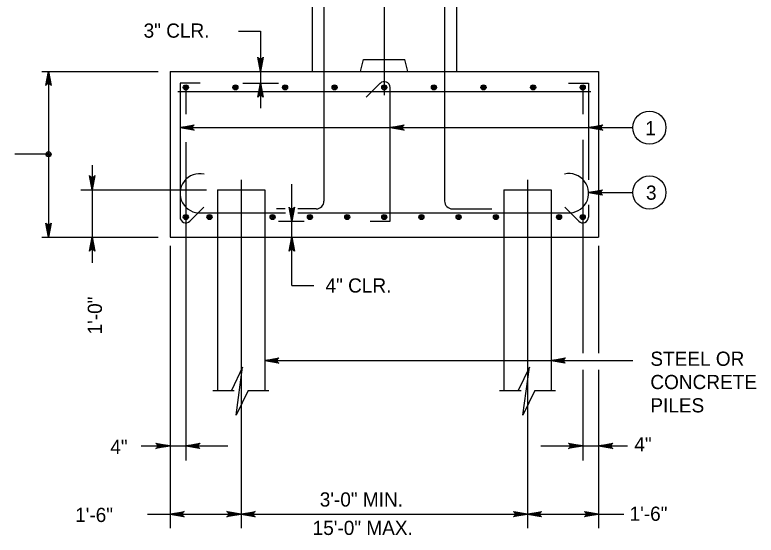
# Model space of a CAD drawing. Extents: x 646165 to 651486, y 296916 to 299292.
# Drawn here: x 650911.5 to 651068, y 299114.9 to 299224.8 of the extents above; entities that cross this region are included whole.
import ezdxf

# ---------------------------------------------------------------- set-up
doc = ezdxf.new("R2010")
doc.units = 0
for name, color, linetype in [('50', 7, 'Continuous'), ('51', 7, 'Continuous'), ('52', 7, 'Continuous'), ('53', 7, 'Continuous'), ('54', 7, 'Continuous'), ('61', 7, 'Continuous')]:
    doc.layers.add(name, color=color, linetype=linetype)

msp = doc.modelspace()

# ---------------------------------------------------------------- linework, layer by layer
at = {"layer": '50'}
for p, q in [((650989.51, 299253.96), (650989.51, 299207.88)), ((650947.61, 299197.9), (650947.61, 299130.73)), ((651031.41, 299198.39), (651031.41, 299153.4)), ((650959.28, 299190.01), (650959.28, 299116.44)), ((651019.74, 299190.01), (651019.74, 299116.44)), ((651031.41, 299149.83), (651031.41, 299130.73))]:
    msp.add_line(p, q, dxfattribs=at)
at = {"layer": '51'}
for p, q in [((650974.28, 299257.98), (650974.28, 299212.88)), ((651004.74, 299257.98), (651004.74, 299212.88)), ((650984.51, 299212.88), (650985.15, 299215.38)), ((650985.15, 299215.38), (650993.87, 299215.38)), ((650994.51, 299212.88), (650993.87, 299215.38)), ((650944.28, 299212.88), (650944.28, 299177.88)), ((650944.28, 299212.88), (651034.74, 299212.88)), ((651034.74, 299212.88), (651034.74, 299177.88)), ((650944.28, 299177.88), (651034.74, 299177.88))]:
    msp.add_line(p, q, dxfattribs=at)
at = {"layer": '52'}
for p, q in [((650958.74, 299221.35), (650963.37, 299221.35)), ((650963.37, 299221.35), (650963.37, 299205.12)), ((650917.23, 299212.88), (650941.76, 299212.88)), ((650918.62, 299212.88), (650918.62, 299177.88)), ((650959.62, 299210.38), (650967.15, 299210.38)), ((650947.61, 299209.49), (650947.61, 299203.87)), ((651031.41, 299209.49), (651031.41, 299203.87)), ((650946.39, 299201), (651041.98, 299201)), ((650918.62, 299195.38), (650911.51, 299195.38)), ((650927.85, 299193.04), (650927.85, 299172.45)), ((650969.96, 299167.66), (650969.96, 299189.04)), ((650925.44, 299187.88), (650952.01, 299187.88)), ((651032.63, 299187.31), (651041.98, 299187.31)), ((650967.2, 299181.22), (650972.62, 299181.22)), ((650917.23, 299177.88), (650941.76, 299177.88)), ((650944.28, 299176.06), (650944.28, 299116.44)), ((651034.74, 299176.06), (651034.74, 299153.4)), ((650969.96, 299167.66), (650974.66, 299167.66)), ((650964.28, 299151.8), (651041.98, 299151.8)), ((651034.74, 299149.83), (651034.74, 299116.44)), ((650953.29, 299145.48), (650957.85, 299145.48)), ((650960.77, 299145.48), (650965.11, 299145.48)), ((651013.82, 299145.48), (651018.38, 299145.48)), ((651021.3, 299145.48), (651025.63, 299145.48)), ((650938.21, 299133.78), (650956.5, 299133.78)), ((651022.53, 299133.78), (651040.88, 299133.78)), ((650939.49, 299119.38), (650959.28, 299119.38)), ((650959.28, 299119.38), (651019.74, 299119.38)), ((651019.74, 299119.38), (651040.11, 299119.38))]:
    msp.add_line(p, q, dxfattribs=at)
for points in [[(650963.37, 299212.88), (650962.81, 299215.87), (650962.89, 299215.75), (650962.97, 299215.64), (650963.07, 299215.58), (650963.17, 299215.52), (650963.27, 299215.5), (650963.37, 299215.48), (650963.47, 299215.5), (650963.57, 299215.52), (650963.67, 299215.58), (650963.77, 299215.64), (650963.85, 299215.75), (650963.93, 299215.87), (650963.37, 299212.88), (650963.85, 299215.75), (650963.77, 299215.64), (650963.37, 299212.88), (650963.67, 299215.58), (650963.57, 299215.52), (650963.37, 299212.88), (650963.47, 299215.5), (650963.37, 299215.48), (650963.37, 299212.88), (650963.27, 299215.5), (650963.17, 299215.52), (650963.37, 299212.88), (650963.07, 299215.58), (650962.97, 299215.64), (650963.37, 299212.88), (650962.89, 299215.75)], [(650918.62, 299212.88), (650919.18, 299209.9), (650919.1, 299210.02), (650919.02, 299210.13), (650918.92, 299210.19), (650918.82, 299210.25), (650918.72, 299210.27), (650918.62, 299210.28), (650918.52, 299210.27), (650918.42, 299210.25), (650918.32, 299210.19), (650918.22, 299210.13), (650918.14, 299210.02), (650918.06, 299209.9), (650918.62, 299212.88), (650918.14, 299210.02), (650918.22, 299210.13), (650918.62, 299212.88), (650918.32, 299210.19), (650918.42, 299210.25), (650918.62, 299212.88), (650918.52, 299210.27), (650918.62, 299210.28), (650918.62, 299212.88), (650918.72, 299210.27), (650918.82, 299210.25), (650918.62, 299212.88), (650918.92, 299210.19), (650919.02, 299210.13), (650918.62, 299212.88), (650919.1, 299210.02)], [(650963.37, 299210.38), (650963.93, 299207.4), (650963.85, 299207.52), (650963.77, 299207.63), (650963.67, 299207.69), (650963.57, 299207.75), (650963.47, 299207.77), (650963.37, 299207.78), (650963.27, 299207.77), (650963.17, 299207.75), (650963.07, 299207.69), (650962.97, 299207.63), (650962.89, 299207.52), (650962.81, 299207.4), (650963.37, 299210.38), (650962.89, 299207.52), (650962.97, 299207.63), (650963.37, 299210.38), (650963.07, 299207.69), (650963.17, 299207.75), (650963.37, 299210.38), (650963.27, 299207.77), (650963.37, 299207.78), (650963.37, 299210.38), (650963.47, 299207.77), (650963.57, 299207.75), (650963.37, 299210.38), (650963.67, 299207.69), (650963.77, 299207.63), (650963.37, 299210.38), (650963.85, 299207.52)], [(650946.39, 299201), (650949.37, 299201.56), (650949.25, 299201.48), (650949.14, 299201.4), (650949.08, 299201.3), (650949.02, 299201.2), (650949, 299201.1), (650948.99, 299201), (650949, 299200.9), (650949.02, 299200.8), (650949.08, 299200.7), (650949.14, 299200.6), (650949.25, 299200.52), (650949.37, 299200.44), (650946.39, 299201), (650949.25, 299200.52), (650949.14, 299200.6), (650946.39, 299201), (650949.08, 299200.7), (650949.02, 299200.8), (650946.39, 299201), (650949, 299200.9), (650948.99, 299201), (650946.39, 299201), (650949, 299201.1), (650949.02, 299201.2), (650946.39, 299201), (650949.08, 299201.3), (650949.14, 299201.4), (650946.39, 299201), (650949.25, 299201.48)], [(650990.73, 299201), (650993.71, 299201.56), (650993.6, 299201.48), (650993.49, 299201.4), (650993.43, 299201.3), (650993.37, 299201.2), (650993.35, 299201.1), (650993.33, 299201), (650993.35, 299200.9), (650993.37, 299200.8), (650993.43, 299200.7), (650993.49, 299200.6), (650993.6, 299200.52), (650993.71, 299200.44), (650990.73, 299201), (650993.6, 299200.52), (650993.49, 299200.6), (650990.73, 299201), (650993.43, 299200.7), (650993.37, 299200.8), (650990.73, 299201), (650993.35, 299200.9), (650993.33, 299201), (650990.73, 299201), (650993.35, 299201.1), (650993.37, 299201.2), (650990.73, 299201), (650993.43, 299201.3), (650993.49, 299201.4), (650990.73, 299201), (650993.6, 299201.48)], [(651032.63, 299201), (651035.62, 299201.56), (651035.5, 299201.48), (651035.39, 299201.4), (651035.33, 299201.3), (651035.27, 299201.2), (651035.25, 299201.1), (651035.23, 299201), (651035.25, 299200.9), (651035.27, 299200.8), (651035.33, 299200.7), (651035.39, 299200.6), (651035.5, 299200.52), (651035.62, 299200.44), (651032.63, 299201), (651035.5, 299200.52), (651035.39, 299200.6), (651032.63, 299201), (651035.33, 299200.7), (651035.27, 299200.8), (651032.63, 299201), (651035.25, 299200.9), (651035.23, 299201), (651032.63, 299201), (651035.25, 299201.1), (651035.27, 299201.2), (651032.63, 299201), (651035.33, 299201.3), (651035.39, 299201.4), (651032.63, 299201), (651035.5, 299201.48)], [(650927.85, 299187.88), (650927.29, 299190.87), (650927.37, 299190.75), (650927.45, 299190.64), (650927.55, 299190.58), (650927.65, 299190.52), (650927.75, 299190.5), (650927.85, 299190.48), (650927.95, 299190.5), (650928.05, 299190.52), (650928.15, 299190.58), (650928.25, 299190.64), (650928.33, 299190.75), (650928.41, 299190.87), (650927.85, 299187.88), (650928.33, 299190.75), (650928.25, 299190.64), (650927.85, 299187.88), (650928.15, 299190.58), (650928.05, 299190.52), (650927.85, 299187.88), (650927.95, 299190.5), (650927.85, 299190.48), (650927.85, 299187.88), (650927.75, 299190.5), (650927.65, 299190.52), (650927.85, 299187.88), (650927.55, 299190.58), (650927.45, 299190.64), (650927.85, 299187.88), (650927.37, 299190.75)], [(651032.63, 299187.31), (651035.61, 299187.87), (651035.5, 299187.79), (651035.39, 299187.71), (651035.33, 299187.61), (651035.27, 299187.51), (651035.25, 299187.41), (651035.23, 299187.31), (651035.25, 299187.21), (651035.27, 299187.11), (651035.33, 299187.01), (651035.39, 299186.91), (651035.5, 299186.83), (651035.61, 299186.75), (651032.63, 299187.31), (651035.5, 299186.83), (651035.39, 299186.91), (651032.63, 299187.31), (651035.33, 299187.01), (651035.27, 299187.11), (651032.63, 299187.31), (651035.25, 299187.21), (651035.23, 299187.31), (651032.63, 299187.31), (651035.25, 299187.41), (651035.27, 299187.51), (651032.63, 299187.31), (651035.33, 299187.61), (651035.39, 299187.71), (651032.63, 299187.31), (651035.5, 299187.79)], [(650969.96, 299181.22), (650969.4, 299184.2), (650969.48, 299184.08), (650969.56, 299183.97), (650969.66, 299183.91), (650969.76, 299183.85), (650969.86, 299183.83), (650969.96, 299183.82), (650970.06, 299183.83), (650970.16, 299183.85), (650970.26, 299183.91), (650970.36, 299183.97), (650970.44, 299184.08), (650970.52, 299184.2), (650969.96, 299181.22), (650970.44, 299184.08), (650970.36, 299183.97), (650969.96, 299181.22), (650970.26, 299183.91), (650970.16, 299183.85), (650969.96, 299181.22), (650970.06, 299183.83), (650969.96, 299183.82), (650969.96, 299181.22), (650969.86, 299183.83), (650969.76, 299183.85), (650969.96, 299181.22), (650969.66, 299183.91), (650969.56, 299183.97), (650969.96, 299181.22), (650969.48, 299184.08)], [(650918.62, 299177.88), (650918.06, 299180.86), (650918.14, 299180.75), (650918.22, 299180.63), (650918.32, 299180.58), (650918.42, 299180.52), (650918.52, 299180.5), (650918.62, 299180.48), (650918.72, 299180.5), (650918.82, 299180.52), (650918.92, 299180.58), (650919.02, 299180.63), (650919.1, 299180.75), (650919.18, 299180.86), (650918.62, 299177.88), (650919.1, 299180.75), (650919.02, 299180.63), (650918.62, 299177.88), (650918.92, 299180.58), (650918.82, 299180.52), (650918.62, 299177.88), (650918.72, 299180.5), (650918.62, 299180.48), (650918.62, 299177.88), (650918.52, 299180.5), (650918.42, 299180.52), (650918.62, 299177.88), (650918.32, 299180.58), (650918.22, 299180.63), (650918.62, 299177.88), (650918.14, 299180.75)], [(650918.62, 299177.88), (650918.06, 299180.86), (650918.14, 299180.75), (650918.22, 299180.63), (650918.32, 299180.58), (650918.42, 299180.52), (650918.52, 299180.5), (650918.62, 299180.48), (650918.72, 299180.5), (650918.82, 299180.52), (650918.92, 299180.58), (650919.02, 299180.63), (650919.1, 299180.75), (650919.18, 299180.86), (650918.62, 299177.88), (650919.1, 299180.75), (650919.02, 299180.63), (650918.62, 299177.88), (650918.92, 299180.58), (650918.82, 299180.52), (650918.62, 299177.88), (650918.72, 299180.5), (650918.62, 299180.48), (650918.62, 299177.88), (650918.52, 299180.5), (650918.42, 299180.52), (650918.62, 299177.88), (650918.32, 299180.58), (650918.22, 299180.63), (650918.62, 299177.88), (650918.14, 299180.75)], [(650927.85, 299177.88), (650928.41, 299174.9), (650928.33, 299175.01), (650928.25, 299175.13), (650928.15, 299175.19), (650928.05, 299175.25), (650927.95, 299175.27), (650927.85, 299175.28), (650927.75, 299175.27), (650927.65, 299175.25), (650927.55, 299175.19), (650927.45, 299175.13), (650927.37, 299175.01), (650927.29, 299174.9), (650927.85, 299177.88), (650927.37, 299175.01), (650927.45, 299175.13), (650927.85, 299177.88), (650927.55, 299175.19), (650927.65, 299175.25), (650927.85, 299177.88), (650927.75, 299175.27), (650927.85, 299175.28), (650927.85, 299177.88), (650927.95, 299175.27), (650928.05, 299175.25), (650927.85, 299177.88), (650928.15, 299175.19), (650928.25, 299175.13), (650927.85, 299177.88), (650928.33, 299175.01)], [(650969.96, 299177.88), (650970.52, 299174.9), (650970.44, 299175.01), (650970.36, 299175.13), (650970.26, 299175.19), (650970.16, 299175.25), (650970.06, 299175.27), (650969.96, 299175.28), (650969.86, 299175.27), (650969.76, 299175.25), (650969.66, 299175.19), (650969.56, 299175.13), (650969.48, 299175.01), (650969.4, 299174.9), (650969.96, 299177.88), (650969.48, 299175.01), (650969.56, 299175.13), (650969.96, 299177.88), (650969.66, 299175.19), (650969.76, 299175.25), (650969.96, 299177.88), (650969.86, 299175.27), (650969.96, 299175.28), (650969.96, 299177.88), (650970.06, 299175.27), (650970.16, 299175.25), (650969.96, 299177.88), (650970.26, 299175.19), (650970.36, 299175.13), (650969.96, 299177.88), (650970.44, 299175.01)], [(650964.28, 299151.8), (650967.26, 299152.36), (650967.14, 299152.28), (650967.03, 299152.2), (650966.97, 299152.1), (650966.91, 299152), (650966.89, 299151.9), (650966.88, 299151.8), (650966.89, 299151.7), (650966.91, 299151.6), (650966.97, 299151.5), (650967.03, 299151.4), (650967.14, 299151.32), (650967.26, 299151.24), (650964.28, 299151.8), (650967.14, 299151.32), (650967.03, 299151.4), (650964.28, 299151.8), (650966.97, 299151.5), (650966.91, 299151.6), (650964.28, 299151.8), (650966.89, 299151.7), (650966.88, 299151.8), (650964.28, 299151.8), (650966.89, 299151.9), (650966.91, 299152), (650964.28, 299151.8), (650966.97, 299152.1), (650967.03, 299152.2), (650964.28, 299151.8), (650967.14, 299152.28)], [(651024.74, 299151.8), (651027.73, 299152.36), (651027.61, 299152.28), (651027.5, 299152.2), (651027.44, 299152.1), (651027.38, 299152), (651027.36, 299151.9), (651027.34, 299151.8), (651027.36, 299151.7), (651027.38, 299151.6), (651027.44, 299151.5), (651027.5, 299151.4), (651027.61, 299151.32), (651027.73, 299151.24), (651024.74, 299151.8), (651027.61, 299151.32), (651027.5, 299151.4), (651024.74, 299151.8), (651027.44, 299151.5), (651027.38, 299151.6), (651024.74, 299151.8), (651027.36, 299151.7), (651027.34, 299151.8), (651024.74, 299151.8), (651027.36, 299151.9), (651027.38, 299152), (651024.74, 299151.8), (651027.44, 299152.1), (651027.5, 299152.2), (651024.74, 299151.8), (651027.61, 299152.28)], [(650960.77, 299145.48), (650958.23, 299140.29), (650959.61, 299150.44), (650957.25, 299145.48)], [(651021.3, 299145.48), (651018.76, 299140.29), (651020.14, 299150.44), (651017.78, 299145.48)], [(650944.28, 299133.78), (650941.29, 299133.22), (650941.41, 299133.3), (650941.52, 299133.38), (650941.58, 299133.48), (650941.64, 299133.58), (650941.66, 299133.68), (650941.68, 299133.78), (650941.66, 299133.88), (650941.64, 299133.98), (650941.58, 299134.08), (650941.52, 299134.18), (650941.41, 299134.26), (650941.29, 299134.34), (650944.28, 299133.78), (650941.41, 299134.26), (650941.52, 299134.18), (650944.28, 299133.78), (650941.58, 299134.08), (650941.64, 299133.98), (650944.28, 299133.78), (650941.66, 299133.88), (650941.68, 299133.78), (650944.28, 299133.78), (650941.66, 299133.68), (650941.64, 299133.58), (650944.28, 299133.78), (650941.58, 299133.48), (650941.52, 299133.38), (650944.28, 299133.78), (650941.41, 299133.3)], [(650947.61, 299133.78), (650950.59, 299134.34), (650950.48, 299134.26), (650950.36, 299134.18), (650950.3, 299134.08), (650950.24, 299133.98), (650950.23, 299133.88), (650950.21, 299133.78), (650950.23, 299133.68), (650950.24, 299133.58), (650950.3, 299133.48), (650950.36, 299133.38), (650950.48, 299133.3), (650950.59, 299133.22), (650947.61, 299133.78), (650950.48, 299133.3), (650950.36, 299133.38), (650947.61, 299133.78), (650950.3, 299133.48), (650950.24, 299133.58), (650947.61, 299133.78), (650950.23, 299133.68), (650950.21, 299133.78), (650947.61, 299133.78), (650950.23, 299133.88), (650950.24, 299133.98), (650947.61, 299133.78), (650950.3, 299134.08), (650950.36, 299134.18), (650947.61, 299133.78), (650950.48, 299134.26)], [(651031.41, 299133.78), (651028.43, 299133.22), (651028.54, 299133.3), (651028.66, 299133.38), (651028.72, 299133.48), (651028.78, 299133.58), (651028.79, 299133.68), (651028.81, 299133.78), (651028.79, 299133.88), (651028.78, 299133.98), (651028.72, 299134.08), (651028.66, 299134.18), (651028.54, 299134.26), (651028.43, 299134.34), (651031.41, 299133.78), (651028.54, 299134.26), (651028.66, 299134.18), (651031.41, 299133.78), (651028.72, 299134.08), (651028.78, 299133.98), (651031.41, 299133.78), (651028.79, 299133.88), (651028.81, 299133.78), (651031.41, 299133.78), (651028.79, 299133.68), (651028.78, 299133.58), (651031.41, 299133.78), (651028.72, 299133.48), (651028.66, 299133.38), (651031.41, 299133.78), (651028.54, 299133.3)], [(651034.74, 299133.78), (651037.73, 299134.34), (651037.61, 299134.26), (651037.5, 299134.18), (651037.44, 299134.08), (651037.38, 299133.98), (651037.36, 299133.88), (651037.34, 299133.78), (651037.36, 299133.68), (651037.38, 299133.58), (651037.44, 299133.48), (651037.5, 299133.38), (651037.61, 299133.3), (651037.73, 299133.22), (651034.74, 299133.78), (651037.61, 299133.3), (651037.5, 299133.38), (651034.74, 299133.78), (651037.44, 299133.48), (651037.38, 299133.58), (651034.74, 299133.78), (651037.36, 299133.68), (651037.34, 299133.78), (651034.74, 299133.78), (651037.36, 299133.88), (651037.38, 299133.98), (651034.74, 299133.78), (651037.44, 299134.08), (651037.5, 299134.18), (651034.74, 299133.78), (651037.61, 299134.26)], [(650944.28, 299119.38), (650947.26, 299119.94), (650947.14, 299119.86), (650947.03, 299119.78), (650946.97, 299119.68), (650946.91, 299119.58), (650946.89, 299119.48), (650946.88, 299119.38), (650946.89, 299119.28), (650946.91, 299119.18), (650946.97, 299119.08), (650947.03, 299118.98), (650947.14, 299118.9), (650947.26, 299118.82), (650944.28, 299119.38), (650947.14, 299118.9), (650947.03, 299118.98), (650944.28, 299119.38), (650946.97, 299119.08), (650946.91, 299119.18), (650944.28, 299119.38), (650946.89, 299119.28), (650946.88, 299119.38), (650944.28, 299119.38), (650946.89, 299119.48), (650946.91, 299119.58), (650944.28, 299119.38), (650946.97, 299119.68), (650947.03, 299119.78), (650944.28, 299119.38), (650947.14, 299119.86)], [(650959.28, 299119.38), (650956.29, 299118.82), (650956.41, 299118.9), (650956.52, 299118.98), (650956.58, 299119.08), (650956.64, 299119.18), (650956.66, 299119.28), (650956.68, 299119.38), (650956.66, 299119.48), (650956.64, 299119.58), (650956.58, 299119.68), (650956.52, 299119.78), (650956.41, 299119.86), (650956.29, 299119.94), (650959.28, 299119.38), (650956.41, 299119.86), (650956.52, 299119.78), (650959.28, 299119.38), (650956.58, 299119.68), (650956.64, 299119.58), (650959.28, 299119.38), (650956.66, 299119.48), (650956.68, 299119.38), (650959.28, 299119.38), (650956.66, 299119.28), (650956.64, 299119.18), (650959.28, 299119.38), (650956.58, 299119.08), (650956.52, 299118.98), (650959.28, 299119.38), (650956.41, 299118.9)], [(650959.28, 299119.38), (650962.26, 299119.94), (650962.14, 299119.86), (650962.03, 299119.78), (650961.97, 299119.68), (650961.91, 299119.58), (650961.89, 299119.48), (650961.88, 299119.38), (650961.89, 299119.28), (650961.91, 299119.18), (650961.97, 299119.08), (650962.03, 299118.98), (650962.14, 299118.9), (650962.26, 299118.82), (650959.28, 299119.38), (650962.14, 299118.9), (650962.03, 299118.98), (650959.28, 299119.38), (650961.97, 299119.08), (650961.91, 299119.18), (650959.28, 299119.38), (650961.89, 299119.28), (650961.88, 299119.38), (650959.28, 299119.38), (650961.89, 299119.48), (650961.91, 299119.58), (650959.28, 299119.38), (650961.97, 299119.68), (650962.03, 299119.78), (650959.28, 299119.38), (650962.14, 299119.86)], [(651019.74, 299119.38), (651016.76, 299118.82), (651016.88, 299118.9), (651016.99, 299118.98), (651017.05, 299119.08), (651017.11, 299119.18), (651017.13, 299119.28), (651017.14, 299119.38), (651017.13, 299119.48), (651017.11, 299119.58), (651017.05, 299119.68), (651016.99, 299119.78), (651016.88, 299119.86), (651016.76, 299119.94), (651019.74, 299119.38), (651016.88, 299119.86), (651016.99, 299119.78), (651019.74, 299119.38), (651017.05, 299119.68), (651017.11, 299119.58), (651019.74, 299119.38), (651017.13, 299119.48), (651017.14, 299119.38), (651019.74, 299119.38), (651017.13, 299119.28), (651017.11, 299119.18), (651019.74, 299119.38), (651017.05, 299119.08), (651016.99, 299118.98), (651019.74, 299119.38), (651016.88, 299118.9)], [(651019.74, 299119.38), (651022.73, 299119.94), (651022.61, 299119.86), (651022.5, 299119.78), (651022.44, 299119.68), (651022.38, 299119.58), (651022.36, 299119.48), (651022.34, 299119.38), (651022.36, 299119.28), (651022.38, 299119.18), (651022.44, 299119.08), (651022.5, 299118.98), (651022.61, 299118.9), (651022.73, 299118.82), (651019.74, 299119.38), (651022.61, 299118.9), (651022.5, 299118.98), (651019.74, 299119.38), (651022.44, 299119.08), (651022.38, 299119.18), (651019.74, 299119.38), (651022.36, 299119.28), (651022.34, 299119.38), (651019.74, 299119.38), (651022.36, 299119.48), (651022.38, 299119.58), (651019.74, 299119.38), (651022.44, 299119.68), (651022.5, 299119.78), (651019.74, 299119.38), (651022.61, 299119.86)], [(651034.74, 299119.38), (651031.76, 299118.82), (651031.88, 299118.9), (651031.99, 299118.98), (651032.05, 299119.08), (651032.11, 299119.18), (651032.13, 299119.28), (651032.14, 299119.38), (651032.13, 299119.48), (651032.11, 299119.58), (651032.05, 299119.68), (651031.99, 299119.78), (651031.88, 299119.86), (651031.76, 299119.94), (651034.74, 299119.38), (651031.88, 299119.86), (651031.99, 299119.78), (651034.74, 299119.38), (651032.05, 299119.68), (651032.11, 299119.58), (651034.74, 299119.38), (651032.13, 299119.48), (651032.14, 299119.38), (651034.74, 299119.38), (651032.13, 299119.28), (651032.11, 299119.18), (651034.74, 299119.38), (651032.05, 299119.08), (651031.99, 299118.98), (651034.74, 299119.38), (651031.88, 299118.9)]]:
    msp.add_lwpolyline(points, dxfattribs=at)
for centre, radius in [((651045.48, 299201), 3.5), ((650918.62, 299195.38), 0.533), ((650918.62, 299195.38), 0.267), ((651045.48, 299187.31), 3.5)]:
    msp.add_circle(centre, radius, dxfattribs=at)
at = {"layer": '54'}
for p, q in [((650976.78, 299257.98), (650976.78, 299185.5)), ((651002.24, 299257.98), (651002.24, 299185.5)), ((650950.62, 299210.38), (650946.39, 299210.38)), ((650946.39, 299210.38), (650946.39, 299182.11)), ((650988.65, 299210.36), (650985.7, 299207.41)), ((651028.4, 299210.38), (651032.63, 299210.38)), ((651032.63, 299210.38), (651032.63, 299189.99)), ((650945.94, 299208.6), (651033.08, 299208.6)), ((650990.73, 299181.22), (650990.73, 299209.49)), ((650948.47, 299181.24), (650951.42, 299184.19)), ((650968.56, 299183.83), (650966.78, 299183.83)), ((650975.11, 299183.83), (650971.29, 299183.83)), ((651003.91, 299183.83), (651012.24, 299183.83)), ((651030.55, 299181.24), (651027.6, 299184.19)), ((651032.63, 299184.7), (651032.63, 299182.11)), ((650950.89, 299183), (650968.62, 299183)), ((650971.23, 299183), (651028.15, 299183)), ((650986.5, 299181.22), (650990.73, 299181.22))]:
    msp.add_line(p, q, dxfattribs=at)
for centre, radius in [((650947.61, 299209.49), 0.533), ((650958.08, 299209.49), 0.533), ((650968.56, 299209.49), 0.533), ((650979.03, 299209.49), 0.533), ((650989.51, 299209.49), 0.533), ((650999.99, 299209.49), 0.533), ((651010.46, 299209.49), 0.533), ((651020.94, 299209.49), 0.533), ((651031.41, 299209.49), 0.533), ((650947.61, 299209.49), 0.4), ((650947.61, 299209.49), 0.267), ((650947.61, 299209.49), 0.133), ((650958.08, 299209.49), 0.4), ((650958.08, 299209.49), 0.267), ((650958.08, 299209.49), 0.133), ((650968.56, 299209.49), 0.4), ((650968.56, 299209.49), 0.267), ((650968.56, 299209.49), 0.133), ((650979.03, 299209.49), 0.4), ((650979.03, 299209.49), 0.267), ((650979.03, 299209.49), 0.133), ((650989.51, 299209.49), 0.4), ((650989.51, 299209.49), 0.267), ((650989.51, 299209.49), 0.133), ((650999.99, 299209.49), 0.4), ((650999.99, 299209.49), 0.267), ((650999.99, 299209.49), 0.133), ((651010.46, 299209.49), 0.4), ((651010.46, 299209.49), 0.267), ((651010.46, 299209.49), 0.133), ((651020.94, 299209.49), 0.4), ((651020.94, 299209.49), 0.267), ((651020.94, 299209.49), 0.133), ((651031.41, 299209.49), 0.4), ((651031.41, 299209.49), 0.267), ((651031.41, 299209.49), 0.133), ((650947.61, 299182.11), 0.533), ((650947.61, 299182.11), 0.4), ((650947.61, 299182.11), 0.267), ((650947.61, 299182.11), 0.133), ((650952.61, 299182.11), 0.533), ((650952.61, 299182.11), 0.4), ((650952.61, 299182.11), 0.267), ((650952.61, 299182.11), 0.133), ((650965.94, 299182.11), 0.533), ((650965.94, 299182.11), 0.4), ((650965.94, 299182.11), 0.267), ((650965.94, 299182.11), 0.133), ((650973.81, 299182.11), 0.533), ((650973.81, 299182.11), 0.4), ((650973.81, 299182.11), 0.267), ((650973.81, 299182.11), 0.133), ((650981.68, 299182.11), 0.533), ((650981.68, 299182.11), 0.4), ((650981.68, 299182.11), 0.267), ((650981.68, 299182.11), 0.133), ((650989.51, 299182.11), 0.533), ((650989.51, 299182.11), 0.4), ((650989.51, 299182.11), 0.267), ((650989.51, 299182.11), 0.133), ((650997.34, 299182.11), 0.533), ((650997.34, 299182.11), 0.4), ((650997.34, 299182.11), 0.267), ((650997.34, 299182.11), 0.133), ((651005.21, 299182.11), 0.533), ((651005.21, 299182.11), 0.4), ((651005.21, 299182.11), 0.267), ((651005.21, 299182.11), 0.133), ((651013.08, 299182.11), 0.533), ((651013.08, 299182.11), 0.4), ((651013.08, 299182.11), 0.267), ((651013.08, 299182.11), 0.133), ((651026.41, 299182.11), 0.533), ((651026.41, 299182.11), 0.4), ((651026.41, 299182.11), 0.267), ((651026.41, 299182.11), 0.133), ((651031.41, 299182.11), 0.533), ((651031.41, 299182.11), 0.4), ((651031.41, 299182.11), 0.267), ((651031.41, 299182.11), 0.133)]:
    msp.add_circle(centre, radius, dxfattribs=at)
for centre, radius, start, end in [((650989.51, 299209.49), 1.22, 0, 135), ((650950.55, 299187.13), 4.15, 77.003, 274.6496), ((651028.49, 299187.15), 4.15, 265.3504, 102.997), ((650975.11, 299185.5), 1.67, 270, 0), ((651003.91, 299185.5), 1.67, 180, 270), ((650947.61, 299182.11), 1.22, 180, 315), ((651031.41, 299182.11), 1.22, 225, 0)]:
    msp.add_arc(centre, radius, start, end, dxfattribs=at)
at = {"layer": '61'}
for p, q in [((650954.28, 299187.88), (650964.28, 299187.88)), ((650954.28, 299187.88), (650954.28, 299177.88)), ((650964.28, 299187.88), (650964.28, 299177.88)), ((651014.74, 299187.88), (651024.74, 299187.88)), ((651014.74, 299187.88), (651014.74, 299177.88)), ((651024.74, 299187.88), (651024.74, 299177.88)), ((650954.28, 299177.88), (650954.28, 299145.48)), ((650964.28, 299177.88), (650964.28, 299145.48)), ((651014.74, 299177.88), (651014.74, 299145.48)), ((651024.74, 299177.88), (651024.74, 299145.48))]:
    msp.add_line(p, q, dxfattribs=at)

# ---------------------------------------------------------------- texts
at = {"layer": '53'}
for s, p in [('3" CLR.', (650938.7, 299219.99)), ('1', (651044.62, 299199.4)), ('3', (651044.75, 299185.77)), ('4" CLR.', (650977.1, 299166.17)), ('STEEL OR', (651045.68, 299150.7)), ('CONCRETE', (651045.68, 299145.78)), ('PILES', (651045.68, 299140.86)), ('4"', (650931.67, 299132.08)), ('4"', (651042.3, 299132.62)), ('3\'-0" MIN.', (650975.89, 299120.98)), ('1\'-6"', (650924.25, 299117.72)), ('1\'-6"', (651041.3, 299117.97)), ('15\'-0" MAX.', (650974.39, 299114.98))]:
    msp.add_text(s, height=3, dxfattribs=at).set_placement(p)
msp.add_text('1\'-0"', height=3, rotation=90, dxfattribs=at).set_placement((650929.9, 299157.33))

doc.saveas('drawing.dxf')
